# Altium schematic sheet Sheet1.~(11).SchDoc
size B; SheetNumber: 1; SheetTotal: 1
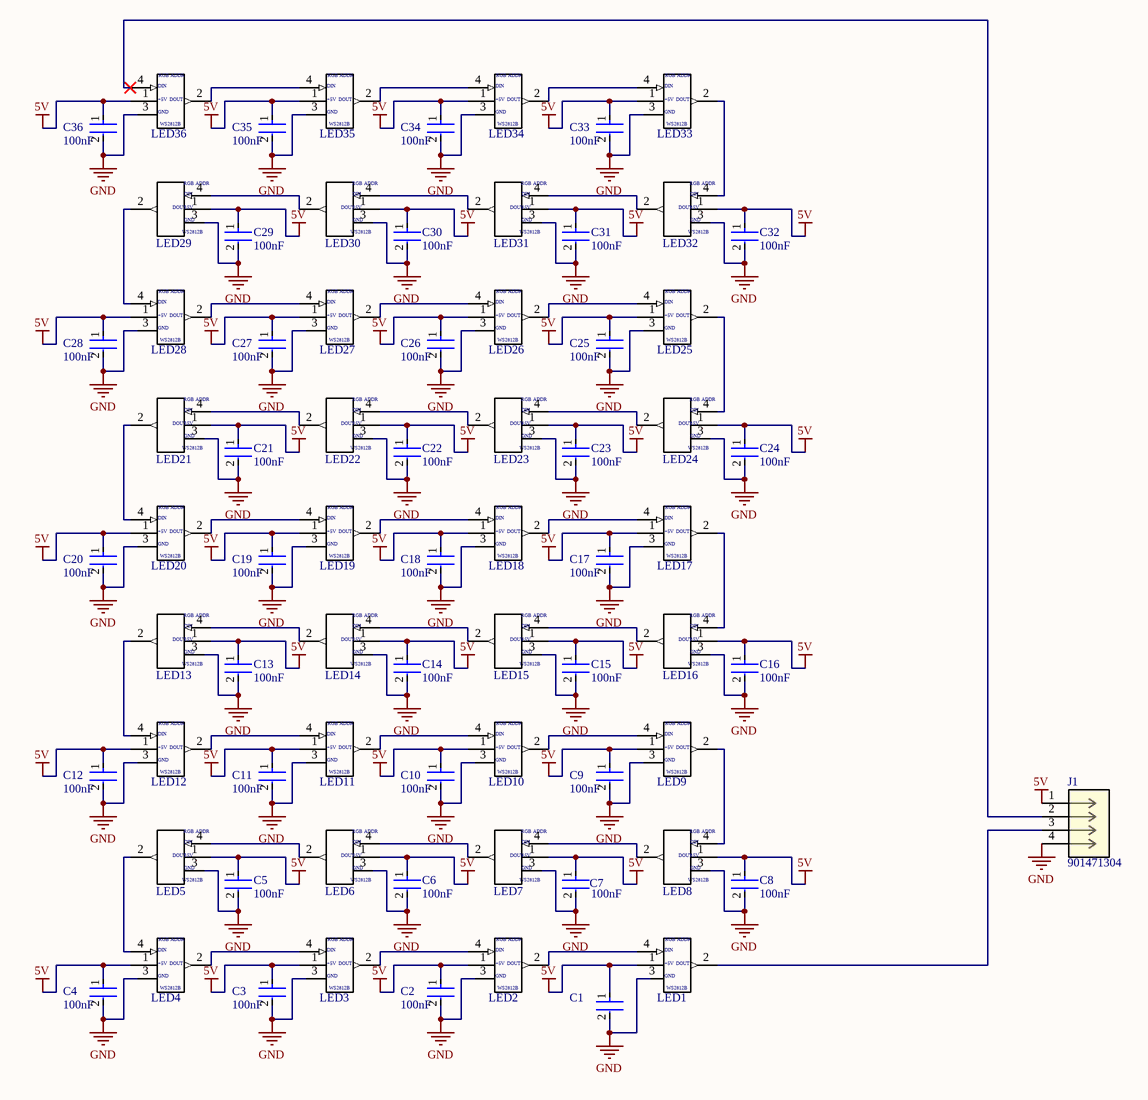
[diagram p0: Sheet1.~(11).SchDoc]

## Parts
C1  CC0603KRX7R6BB104  [FP-CC0603-DA-IPC_B]  (value not drawn)
C2  100nF  [FP-CC0603-DA-IPC_B]
C3  100nF  [FP-CC0603-DA-IPC_B]
C4  100nF  [FP-CC0603-DA-IPC_B]
C5  100nF  [FP-CC0603-DA-IPC_B]
C6  100nF  [FP-CC0603-DA-IPC_B]
C7  100nF  [FP-CC0603-DA-IPC_B]
C8  100nF  [FP-CC0603-DA-IPC_B]
C9  100nF  [FP-CC0603-DA-IPC_B]
C10  100nF  [FP-CC0603-DA-IPC_B]
C11  100nF  [FP-CC0603-DA-IPC_B]
C12  100nF  [FP-CC0603-DA-IPC_B]
C13  100nF  [FP-CC0603-DA-IPC_B]
C14  100nF  [FP-CC0603-DA-IPC_B]
C15  100nF  [FP-CC0603-DA-IPC_B]
C16  100nF  [FP-CC0603-DA-IPC_B]
C17  100nF  [FP-CC0603-DA-IPC_B]
C18  100nF  [FP-CC0603-DA-IPC_B]
C19  100nF  [FP-CC0603-DA-IPC_B]
C20  100nF  [FP-CC0603-DA-IPC_B]
C21  100nF  [FP-CC0603-DA-IPC_B]
C22  100nF  [FP-CC0603-DA-IPC_B]
C23  100nF  [FP-CC0603-DA-IPC_B]
C24  100nF  [FP-CC0603-DA-IPC_B]
C25  100nF  [FP-CC0603-DA-IPC_B]
C26  100nF  [FP-CC0603-DA-IPC_B]
C27  100nF  [FP-CC0603-DA-IPC_B]
C28  100nF  [FP-CC0603-DA-IPC_B]
C29  100nF  [FP-CC0603-DA-IPC_B]
C30  100nF  [FP-CC0603-DA-IPC_B]
C31  100nF  [FP-CC0603-DA-IPC_B]
C32  100nF  [FP-CC0603-DA-IPC_B]
C33  100nF  [FP-CC0603-DA-IPC_B]
C34  100nF  [FP-CC0603-DA-IPC_B]
C35  100nF  [FP-CC0603-DA-IPC_B]
C36  100nF  [FP-CC0603-DA-IPC_B]
J1  901471304  [CONN04_901471304_MOL]
LED1  WS2812B  [*WS2812B_WS2812B(Primary)]  (value not drawn)
LED2  WS2812B  [*WS2812B_WS2812B(Primary)]  (value not drawn)
LED3  WS2812B  [*WS2812B_WS2812B(Primary)]  (value not drawn)
LED4  WS2812B  [*WS2812B_WS2812B(Primary)]  (value not drawn)
LED5  WS2812B  [*WS2812B_WS2812B(Primary)]  (value not drawn)
LED6  WS2812B  [*WS2812B_WS2812B(Primary)]  (value not drawn)
LED7  WS2812B  [*WS2812B_WS2812B(Primary)]  (value not drawn)
LED8  WS2812B  [*WS2812B_WS2812B(Primary)]  (value not drawn)
LED9  WS2812B  [*WS2812B_WS2812B(Primary)]  (value not drawn)
LED10  WS2812B  [*WS2812B_WS2812B(Primary)]  (value not drawn)
LED11  WS2812B  [*WS2812B_WS2812B(Primary)]  (value not drawn)
LED12  WS2812B  [*WS2812B_WS2812B(Primary)]  (value not drawn)
LED13  WS2812B  [*WS2812B_WS2812B(Primary)]  (value not drawn)
LED14  WS2812B  [*WS2812B_WS2812B(Primary)]  (value not drawn)
LED15  WS2812B  [*WS2812B_WS2812B(Primary)]  (value not drawn)
LED16  WS2812B  [*WS2812B_WS2812B(Primary)]  (value not drawn)
LED17  WS2812B  [*WS2812B_WS2812B(Primary)]  (value not drawn)
LED18  WS2812B  [*WS2812B_WS2812B(Primary)]  (value not drawn)
LED19  WS2812B  [*WS2812B_WS2812B(Primary)]  (value not drawn)
LED20  WS2812B  [*WS2812B_WS2812B(Primary)]  (value not drawn)
LED21  WS2812B  [*WS2812B_WS2812B(Primary)]  (value not drawn)
LED22  WS2812B  [*WS2812B_WS2812B(Primary)]  (value not drawn)
LED23  WS2812B  [*WS2812B_WS2812B(Primary)]  (value not drawn)
LED24  WS2812B  [*WS2812B_WS2812B(Primary)]  (value not drawn)
LED25  WS2812B  [*WS2812B_WS2812B(Primary)]  (value not drawn)
LED26  WS2812B  [*WS2812B_WS2812B(Primary)]  (value not drawn)
LED27  WS2812B  [*WS2812B_WS2812B(Primary)]  (value not drawn)
LED28  WS2812B  [*WS2812B_WS2812B(Primary)]  (value not drawn)
LED29  WS2812B  [*WS2812B_WS2812B(Primary)]  (value not drawn)
LED30  WS2812B  [*WS2812B_WS2812B(Primary)]  (value not drawn)
LED31  WS2812B  [*WS2812B_WS2812B(Primary)]  (value not drawn)
LED32  WS2812B  [*WS2812B_WS2812B(Primary)]  (value not drawn)
LED33  WS2812B  [*WS2812B_WS2812B(Primary)]  (value not drawn)
LED34  WS2812B  [*WS2812B_WS2812B(Primary)]  (value not drawn)
LED35  WS2812B  [*WS2812B_WS2812B(Primary)]  (value not drawn)
LED36  WS2812B  [*WS2812B_WS2812B(Primary)]  (value not drawn)

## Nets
5V: C1.1 C2.1 C3.1 C4.1 C5.1 C6.1 C7.1 C8.1 C9.1 C10.1 C11.1 C12.1 C13.1 C14.1 C15.1 C16.1 C17.1 C18.1 C19.1 C20.1 C21.1 C22.1 C23.1 C24.1 C25.1 C26.1 C27.1 C28.1 C29.1 C30.1 C31.1 C32.1 C33.1 C34.1 C35.1 C36.1 J1.1
GND: C1.2 C2.2 C3.2 C4.2 C5.2 C6.2 C7.2 C8.2 C9.2 C10.2 C11.2 C12.2 C13.2 C14.2 C15.2 C16.2 C17.2 C18.2 C19.2 C20.2 C21.2 C22.2 C23.2 C24.2 C25.2 C26.2 C27.2 C28.2 C29.2 C30.2 C31.2 C32.2 C33.2 C34.2 C35.2 C36.2 J1.4
NetJ1_2: J1.2 LED36.4
NetJ1_3: J1.3 LED1.2(DO)
NetLED1_4: LED1.4 LED2.2(DO)
NetLED2_4: LED2.4 LED3.2(DO)
NetLED3_4: LED3.4 LED4.2(DO)
NetLED4_4: LED4.4 LED5.2(DO)
NetLED5_4: LED5.4 LED6.2(DO)
NetLED6_4: LED6.4 LED7.2(DO)
NetLED7_4: LED7.4 LED8.2(DO)
NetLED8_4: LED8.4 LED9.2(DO)
NetLED9_4: LED9.4 LED10.2(DO)
NetLED10_4: LED10.4 LED11.2(DO)
NetLED11_4: LED11.4 LED12.2(DO)
NetLED12_4: LED12.4 LED13.2(DO)
NetLED13_4: LED13.4 LED14.2(DO)
NetLED14_4: LED14.4 LED15.2(DO)
NetLED15_4: LED15.4 LED16.2(DO)
NetLED16_4: LED16.4 LED17.2(DO)
NetLED17_4: LED17.4 LED18.2(DO)
NetLED18_4: LED18.4 LED19.2(DO)
NetLED19_4: LED19.4 LED20.2(DO)
NetLED20_4: LED20.4 LED21.2(DO)
NetLED21_4: LED21.4 LED22.2(DO)
NetLED22_4: LED22.4 LED23.2(DO)
NetLED23_4: LED23.4 LED24.2(DO)
NetLED24_4: LED24.4 LED25.2(DO)
NetLED25_4: LED25.4 LED26.2(DO)
NetLED26_4: LED26.4 LED27.2(DO)
NetLED27_4: LED27.4 LED28.2(DO)
NetLED28_4: LED28.4 LED29.2(DO)
NetLED29_4: LED29.4 LED30.2(DO)
NetLED30_4: LED30.4 LED31.2(DO)
NetLED31_4: LED31.4 LED32.2(DO)
NetLED32_4: LED32.4 LED33.2(DO)
NetLED33_4: LED33.4 LED34.2(DO)
NetLED34_4: LED34.4 LED35.2(DO)
NetLED35_4: LED35.4 LED36.2(DO)

Not connected (* = marked no-connect by the designer): LED1 1 3; LED2 1 3; LED3 1 3; LED4 1 3; LED5 1 3; LED6 1 3; LED7 1 3; LED8 1 3; LED9 1 3; LED10 1 3; LED11 1 3; LED12 1 3; LED13 1 3; LED14 1 3; LED15 1 3; LED16 1 3; LED17 1 3; LED18 1 3; LED19 1 3; LED20 1 3; LED21 1 3; LED22 1 3; LED23 1 3; LED24 1 3; LED25 1 3; LED26 1 3; LED27 1 3; LED28 1 3; LED29 1 3; LED30 1 3; LED31 1 3; LED32 1 3; LED33 1 3; LED34 1 3; LED35 1 3; LED36 1 3

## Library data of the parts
C1 = CMP-03422-001228-1: CAP CER 0.1UF 10V X7R 0603; Manufacturer: YAGEO; Material: Ceramic; Tolerance: 0.1; Capacitance: 100 nF; Temperature Coefficient: 15%; Value: 100 nF
C2-C36 = CMP-03422-001228-1: CAP CER 0.1UF 10V X7R 0603; Manufacturer Part Number: CC0603KRX7R6BB104; Manufacturer: YAGEO; Material: Ceramic; Tolerance: 0.1; Temperature Coefficient: 15%
J1 = 901471304: C-Grid III PCB Receptacle, 2.54mm Pitch, Single Row, Vertical, Shrouded, 4 Circuits, 0.76Âµm Gold (Au) Plating; Manufacturer_Name: Molex
LED1-LED36 = WS2812B: Intelligent control LED integrated light source; MF: Worldsemi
